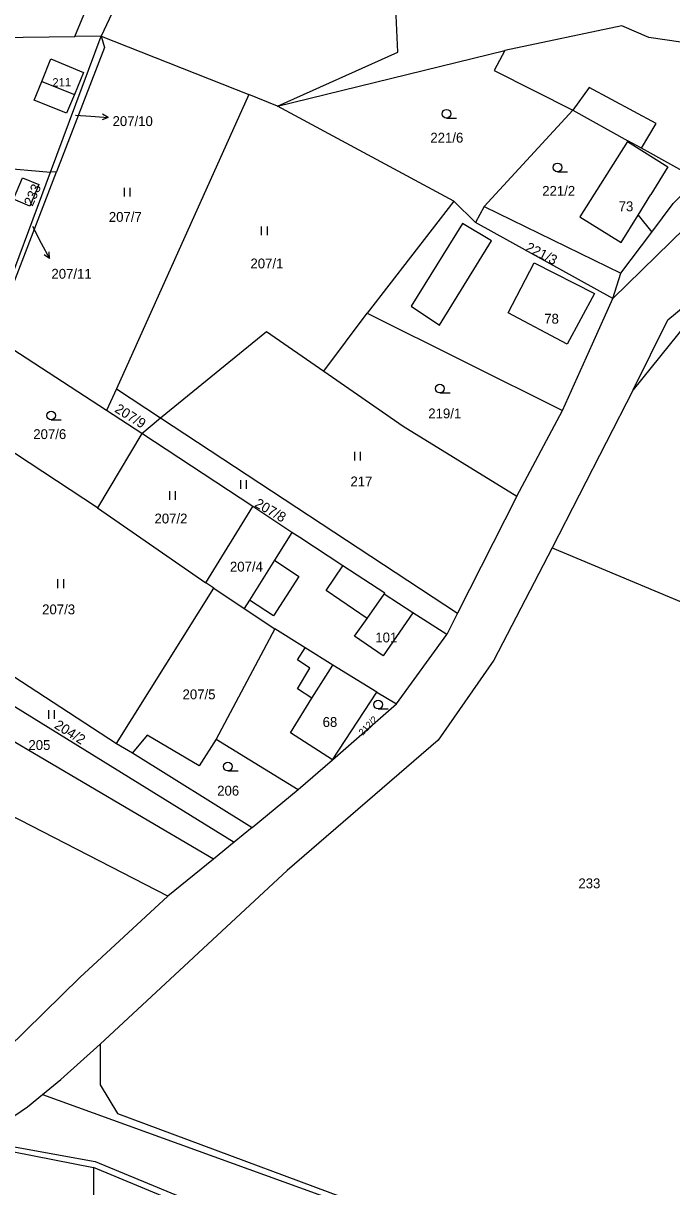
# Model space of a CAD drawing. Extents: x -7483133 to -743907, y -11317770 to -1129777.
# Drawn here: x -746718.8 to -746606.9, y -1132279.3 to -1132078.7 of the extents above; entities that cross this region are included whole.
import ezdxf

# ---------------------------------------------------------------- set-up
doc = ezdxf.new("R2010")
doc.units = 0
for name, color, linetype in [('Hranice parcel', 7, 'Continuous'), ('Parcelní čísla', 7, 'Continuous'), ('Pop  PČ popisy', 7, 'Continuous'), ('Vnitřní kresba', 7, 'Continuous'), ('Značky kultur', 7, 'Continuous')]:
    doc.layers.add(name, color=color, linetype=linetype)

msp = doc.modelspace()

# ---------------------------------------------------------------- linework, layer by layer
at = {"layer": 'Hranice parcel'}
for p, q in [((-746730.14, -1132081.25), (-746709.89, -1132080.97)), ((-746714.1, -1132104.36), (-746705.38, -1132080.91)), ((-746705.38, -1132080.91), (-746709.89, -1132080.97)), ((-746705.38, -1132080.91), (-746679.89, -1132091)), ((-746705.38, -1132080.91), (-746704.8, -1132082.86)), ((-746704.8, -1132082.86), (-746713.07, -1132104.3)), ((-746674.91, -1132092.97), (-746635.72, -1132083.37)), ((-746679.89, -1132091), (-746702.74, -1132141.73)), ((-746674.91, -1132092.97), (-746679.89, -1132091)), ((-746644.51, -1132109.35), (-746674.91, -1132092.97)), ((-746623.94, -1132093.67), (-746639.26, -1132110.3)), ((-746623.94, -1132093.67), (-746614.46, -1132098.94)), ((-746614.46, -1132098.94), (-746614.54, -1132099.07)), ((-746733.1, -1132102.66), (-746714.1, -1132104.36)), ((-746713.07, -1132104.3), (-746714.1, -1132104.36)), ((-746724.55, -1132132.39), (-746714.1, -1132104.36)), ((-746644.51, -1132109.35), (-746659.43, -1132128.69)), ((-746640.76, -1132113.05), (-746644.51, -1132109.35)), ((-746639.26, -1132110.3), (-746640.76, -1132113.05)), ((-746639.26, -1132110.3), (-746615.65, -1132121.76)), ((-746612.7, -1132111.76), (-746610.34, -1132114.69)), ((-746617.06, -1132126.14), (-746640.76, -1132113.05)), ((-746615.65, -1132121.76), (-746610.34, -1132114.69)), ((-746617.06, -1132126.14), (-746615.65, -1132121.76)), ((-746666.94, -1132138.69), (-746659.43, -1132128.69)), ((-746659.43, -1132128.69), (-746625.72, -1132145.44)), ((-746604.23, -1132130.37), (-746613.53, -1132141.89)), ((-746704.42, -1132145.46), (-746724.55, -1132132.39)), ((-746702.74, -1132141.73), (-746704.42, -1132145.46)), ((-746702.74, -1132141.73), (-746695.1, -1132146.75)), ((-746613.53, -1132141.89), (-746627.53, -1132169.14)), ((-746698.35, -1132149.4), (-746704.42, -1132145.46)), ((-746633.63, -1132160.23), (-746625.72, -1132145.44)), ((-746698.35, -1132149.4), (-746695.1, -1132146.75)), ((-746695.1, -1132146.75), (-746643.87, -1132180.43)), ((-746698.35, -1132149.4), (-746706, -1132162.26)), ((-746679.2, -1132162.02), (-746698.35, -1132149.4)), ((-746633.63, -1132160.23), (-746643.87, -1132180.43)), ((-746706, -1132162.26), (-746687.28, -1132175.19)), ((-746687.28, -1132175.19), (-746679.2, -1132162.02)), ((-746672.44, -1132166.48), (-746679.2, -1132162.02)), ((-746627.53, -1132169.14), (-746573.08, -1132191.94)), ((-746702.69, -1132202.89), (-746685.93, -1132176.1)), ((-746685.93, -1132176.1), (-746687.28, -1132175.19)), ((-746685.93, -1132176.1), (-746680.69, -1132179.58)), ((-746738.86, -1132179.39), (-746702.69, -1132202.89)), ((-746680.69, -1132179.58), (-746675.38, -1132183.11)), ((-746643.87, -1132180.43), (-746645.7, -1132184.06)), ((-746743.19, -1132182.42), (-746682.41, -1132219.89)), ((-746675.38, -1132183.11), (-746685.49, -1132202.16)), ((-746654.39, -1132196.03), (-746645.7, -1132184.06)), ((-746665.44, -1132205.68), (-746657.77, -1132194.04)), ((-746657.77, -1132194.04), (-746654.39, -1132196.03)), ((-746665.44, -1132205.68), (-746654.39, -1132196.03)), ((-746693.83, -1132229.18), (-746749.91, -1132200.43)), ((-746685.49, -1132202.16), (-746671.39, -1132210.8)), ((-746702.69, -1132202.89), (-746699.96, -1132204.52)), ((-746699.96, -1132204.52), (-746679.29, -1132217.36)), ((-746671.39, -1132210.8), (-746665.44, -1132205.68)), ((-746679.29, -1132217.36), (-746671.39, -1132210.8)), ((-746679.29, -1132217.36), (-746682.41, -1132219.89)), ((-746682.41, -1132219.89), (-746686, -1132222.81)), ((-746686, -1132222.81), (-746693.83, -1132229.18)), ((-746706.71, -1132276.02), (-746706.66, -1132281.38)), ((-746689.65, -1132283.05), (-746706.71, -1132276.02))]:
    msp.add_line(p, q, dxfattribs=at)
for points in [[(-746709.89, -1132080.97), (-746700.88, -1132059.24), (-746690.31, -1132034.95), (-746646.39, -1131931.6)], [(-746640.16, -1131931.3), (-746678.35, -1132019.74), (-746690.91, -1132050.15), (-746705.38, -1132080.91)], [(-746674.91, -1132092.97), (-746654.17, -1132083.68), (-746655.72, -1132049.5), (-746655.89, -1132035.79), (-746596.68, -1131997.54)], [(-746500.33, -1132067.94), (-746525.66, -1132093.79), (-746540.32, -1132096.18), (-746561.68, -1132093.18), (-746580.81, -1132095.03), (-746587.06, -1132096.88), (-746617.06, -1132126.14)], [(-746599.39, -1132082.82), (-746610.83, -1132081.15), (-746615.53, -1132079.14), (-746635.72, -1132083.37)], [(-746635.72, -1132083.37), (-746637.54, -1132086.86), (-746623.94, -1132093.67)], [(-746711.32, -1132094.22), (-746716.94, -1132091.93), (-746715.63, -1132088.71), (-746714.06, -1132084.83), (-746708.4, -1132087.18), (-746709.98, -1132090.99), (-746711.32, -1132094.22)], [(-746614.54, -1132099.07), (-746622.78, -1132112.05), (-746615.64, -1132116.49), (-746612.7, -1132111.76)], [(-746602.53, -1132105.58), (-746612.12, -1132100.24), (-746614.46, -1132098.94)], [(-746724.55, -1132132.39), (-746722.76, -1132129.43), (-746713.07, -1132104.3)], [(-746718.96, -1132105.32), (-746716.14, -1132106.48), (-746717.68, -1132110.21), (-746720.5, -1132109.04), (-746718.96, -1132105.32)], [(-746610.34, -1132114.69), (-746606.66, -1132109.79), (-746602.53, -1132105.58)], [(-746613.53, -1132141.89), (-746607.56, -1132129.82), (-746596.59, -1132120.74)], [(-746625.72, -1132145.44), (-746620.55, -1132133.99), (-746617.06, -1132126.14)], [(-746695.1, -1132146.75), (-746676.81, -1132131.86), (-746666.94, -1132138.69)], [(-746666.94, -1132138.69), (-746653.23, -1132148.18), (-746633.63, -1132160.23)], [(-746706, -1132162.26), (-746727.28, -1132148.3), (-746738.86, -1132179.39)], [(-746672.44, -1132166.48), (-746675.45, -1132171.26), (-746679.79, -1132178.16), (-746680.69, -1132179.58)], [(-746645.7, -1132184.06), (-746651.6, -1132180.37), (-746656.53, -1132177.13), (-746656.42, -1132176.97), (-746663.67, -1132172.26), (-746671.09, -1132167.37), (-746672.44, -1132166.48)], [(-746627.53, -1132169.14), (-746637.59, -1132188.53), (-746647.21, -1132202.3), (-746673.25, -1132224.8), (-746705.52, -1132254.75)], [(-746657.77, -1132194.04), (-746665.4, -1132189.36), (-746670.13, -1132186.36), (-746675.38, -1132183.11)], [(-746686, -1132222.81), (-746700.07, -1132214.57), (-746729.82, -1132197.08), (-746745.18, -1132187.75)], [(-746685.49, -1132202.16), (-746688.44, -1132206.74), (-746697.45, -1132201.42), (-746699.96, -1132204.52)], [(-746721.51, -1132255.46), (-746709.03, -1132243.21), (-746693.83, -1132229.18)], [(-746733.81, -1132276.07), (-746730.72, -1132274.13), (-746718.09, -1132265.55), (-746715.48, -1132263.41), (-746712.32, -1132260.82), (-746705.52, -1132254.75)], [(-746705.52, -1132254.75), (-746705.52, -1132261.75), (-746702.56, -1132266.68), (-746651.51, -1132285.68), (-746635.38, -1132289.23)], [(-746733.81, -1132276.07), (-746720.42, -1132273.3), (-746706.71, -1132276.02)]]:
    msp.add_lwpolyline(points, dxfattribs=at)
at = {"layer": 'Pop  PČ popisy'}
for p, q in [((-746709.8, -1132094.52), (-746707.14, -1132094.71)), ((-746707.14, -1132094.71), (-746704.15, -1132094.92)), ((-746704.15, -1132094.92), (-746705.18, -1132095.35)), ((-746704.15, -1132094.92), (-746705.11, -1132094.35)), ((-746717.22, -1132113.7), (-746715.7, -1132116.6)), ((-746715.7, -1132116.6), (-746714.29, -1132119.25)), ((-746714.29, -1132119.25), (-746714.32, -1132118.13)), ((-746714.29, -1132119.25), (-746715.2, -1132118.6))]:
    msp.add_line(p, q, dxfattribs=at)
at = {"layer": 'Vnitřní kresba'}
for p, q in [((-746715.63, -1132088.71), (-746709.98, -1132090.99)), ((-746621.16, -1132089.74), (-746623.94, -1132093.67)), ((-746609.59, -1132095.98), (-746621.16, -1132089.74)), ((-746612.12, -1132100.24), (-746609.59, -1132095.98)), ((-746614.54, -1132099.07), (-746607.55, -1132103.47)), ((-746607.55, -1132103.47), (-746610.49, -1132108.2)), ((-746612.7, -1132111.76), (-746610.49, -1132108.2)), ((-746642.98, -1132113.24), (-746651.88, -1132127.45)), ((-746637.99, -1132116.23), (-746642.98, -1132113.24)), ((-746646.97, -1132130.75), (-746637.99, -1132116.23)), ((-746635.14, -1132128.6), (-746630.61, -1132120)), ((-746630.61, -1132120), (-746620.25, -1132125.3)), ((-746620.25, -1132125.3), (-746624.93, -1132134.05)), ((-746651.88, -1132127.45), (-746646.97, -1132130.75)), ((-746624.93, -1132134.05), (-746635.14, -1132128.6)), ((-746675.45, -1132171.26), (-746671.27, -1132174.11)), ((-746666.56, -1132176.49), (-746663.67, -1132172.26)), ((-746671.27, -1132174.11), (-746675.65, -1132180.87)), ((-746659.47, -1132181.31), (-746666.56, -1132176.49)), ((-746675.65, -1132180.87), (-746679.79, -1132178.16)), ((-746659.47, -1132181.31), (-746656.53, -1132177.13)), ((-746651.6, -1132180.37), (-746656.68, -1132187.78)), ((-746661.63, -1132184.39), (-746659.47, -1132181.31)), ((-746656.68, -1132187.78), (-746661.63, -1132184.39)), ((-746671.46, -1132188.47), (-746670.13, -1132186.36)), ((-746669.35, -1132189.9), (-746671.46, -1132188.47)), ((-746671.5, -1132193.47), (-746669.35, -1132189.9)), ((-746668.98, -1132195.04), (-746665.4, -1132189.36)), ((-746668.98, -1132195.04), (-746671.5, -1132193.47)), ((-746672.69, -1132201.07), (-746668.98, -1132195.04)), ((-746665.44, -1132205.68), (-746672.69, -1132201.07)), ((-746715.48, -1132263.41), (-746651.99, -1132286.34)), ((-746721.28, -1132272.26), (-746706.38, -1132274.95)), ((-746706.38, -1132274.95), (-746674.66, -1132288.06))]:
    msp.add_line(p, q, dxfattribs=at)
at = {"layer": 'Značky kultur'}
for p, q in [((-746645.77, -1132095.04), (-746644.02, -1132095.04)), ((-746626.62, -1132104.29), (-746624.87, -1132104.29)), ((-746701.33, -1132108.56), (-746701.33, -1132107.06)), ((-746700.33, -1132108.56), (-746700.33, -1132107.06)), ((-746677.68, -1132115.25), (-746677.68, -1132113.75)), ((-746676.68, -1132115.25), (-746676.68, -1132113.75)), ((-746646.9, -1132142.44), (-746645.15, -1132142.44)), ((-746713.99, -1132147.08), (-746712.24, -1132147.08)), ((-746661.58, -1132154.11), (-746661.58, -1132152.61)), ((-746660.58, -1132154.11), (-746660.58, -1132152.61)), ((-746681.27, -1132158.98), (-746681.27, -1132157.48)), ((-746680.27, -1132158.98), (-746680.27, -1132157.48)), ((-746693.52, -1132160.87), (-746693.52, -1132159.37)), ((-746692.52, -1132160.87), (-746692.52, -1132159.37)), ((-746712.83, -1132176.07), (-746712.83, -1132174.57)), ((-746711.83, -1132176.07), (-746711.83, -1132174.57)), ((-746714.42, -1132198.62), (-746714.42, -1132197.12)), ((-746713.42, -1132198.62), (-746713.42, -1132197.12)), ((-746657.57, -1132196.93), (-746655.82, -1132196.93)), ((-746683.49, -1132207.62), (-746681.74, -1132207.62))]:
    msp.add_line(p, q, dxfattribs=at)
for centre in [(-746645.77, -1132094.29), (-746626.62, -1132103.54), (-746646.9, -1132141.69), (-746713.99, -1132146.33), (-746657.57, -1132196.18), (-746683.49, -1132206.87)]:
    msp.add_circle(centre, 0.75, dxfattribs=at)

# ---------------------------------------------------------------- texts
at = {"layer": 'Parcelní čísla'}
for s, height, rotation, p in [('211', 1.436, 1, (-746713.76, -1132089.61)), ('233', 1.7, 66, (-746717.22, -1132110.36)), ('221/3', 1.7, 333, (-746632.27, -1132117.86)), ('207/9', 1.7, 328, (-746703.16, -1132145.61)), ('207/8', 1.7, 330, (-746679.02, -1132161.97)), ('212/2', 1.14, 46, (-746660.21, -1132201.57)), ('204/2', 1.7, 328, (-746713.59, -1132200.13))]:
    msp.add_text(s, height=height, rotation=rotation, dxfattribs=at).set_placement(p)
for s, p in [('207/10', (-746703.4, -1132096.41)), ('221/6', (-746648.55, -1132099.27)), ('221/2', (-746629.25, -1132108.44)), ('73', (-746616.05, -1132111.1)), ('207/7', (-746704.04, -1132112.93)), ('207/1', (-746679.6, -1132120.96)), ('207/11', (-746713.95, -1132122.74)), ('78', (-746628.9, -1132130.49)), ('219/1', (-746648.91, -1132146.82)), ('207/6', (-746717.08, -1132150.39)), ('217', (-746662.34, -1132158.55)), ('207/2', (-746696.16, -1132164.94)), ('207/4', (-746683.14, -1132173.24)), ('207/3', (-746715.55, -1132180.61)), ('101', (-746658.05, -1132185.45)), ('207/5', (-746691.32, -1132195.26)), ('68', (-746667.14, -1132200.03)), ('205', (-746717.92, -1132204)), ('206', (-746685.34, -1132211.87)), ('233', (-746623, -1132227.85))]:
    msp.add_text(s, height=1.7, dxfattribs=at).set_placement(p)

doc.saveas('drawing.dxf')
